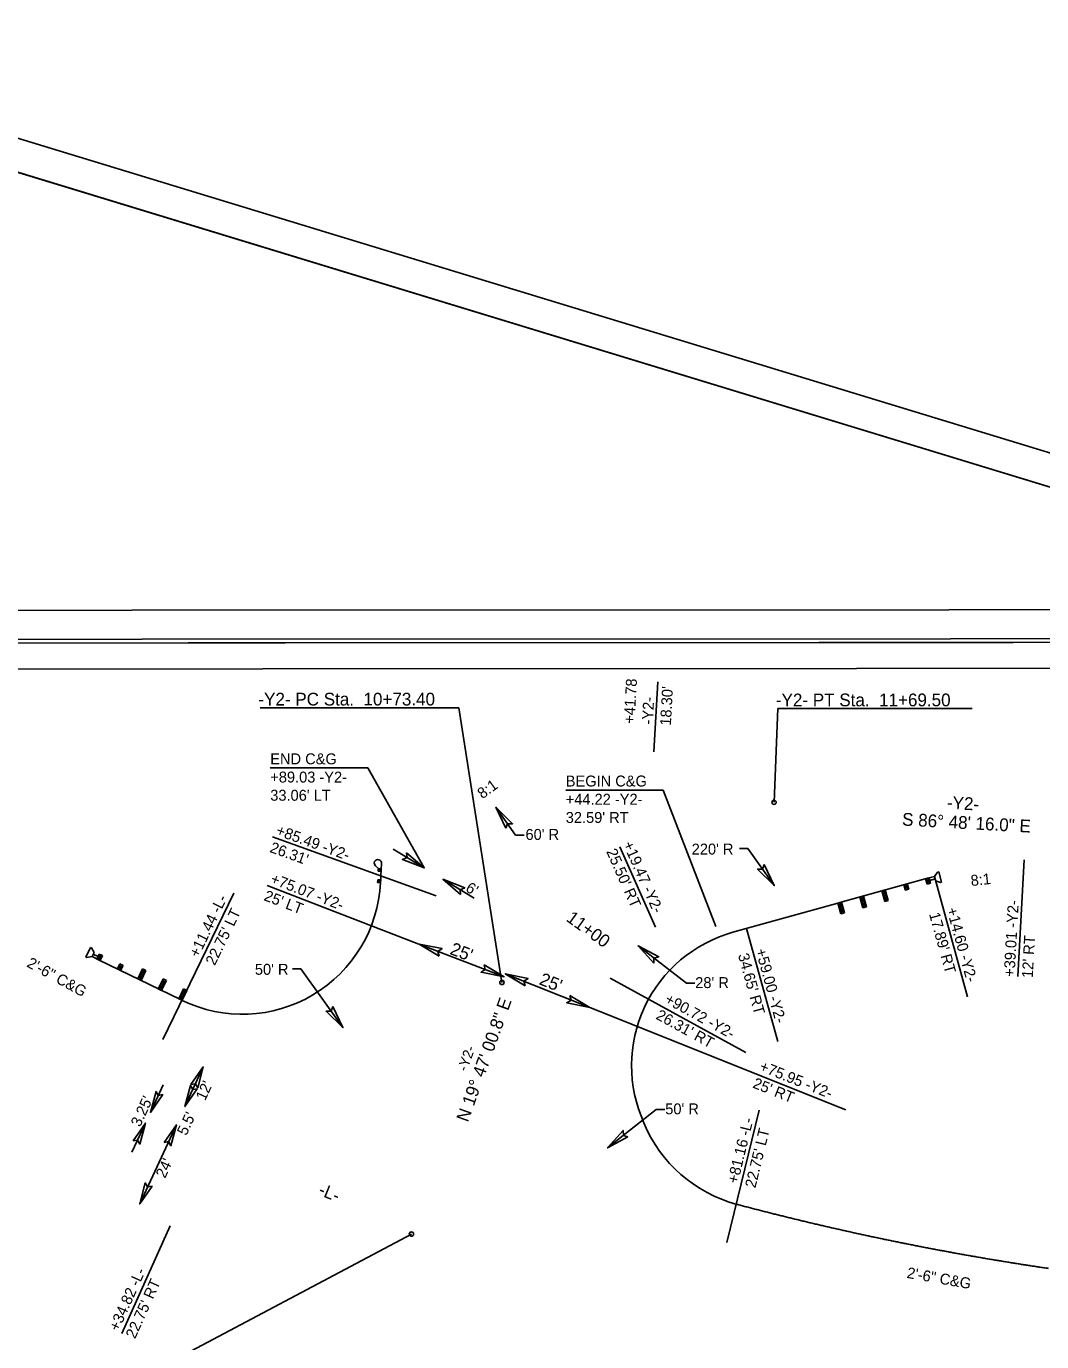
# Model space of a CAD drawing. Extents: x 1443477 to 1619989, y 756574 to 899826.
# Drawn here: x 1619422.9 to 1619701.9, y 898058.9 to 898420 of the extents above; entities that cross this region are included whole.
import ezdxf

# ---------------------------------------------------------------- set-up
doc = ezdxf.new("R2010")
doc.units = 0
for name, color, linetype in [('Default', 7, 'Continuous'), ('Prop Conc 2ft 6in Curb and Gutter', 7, 'Continuous'), ('Prop Dimension', 7, 'Continuous'), ('Prop Guardrail', 7, 'Continuous'), ('Prop Guardrail Anchor Unit CELL', 7, 'Continuous'), ('Prop Horizontal Alignment Direction Label', 7, 'Continuous'), ('Prop Horizontal Alignment Station Label', 7, 'Continuous'), ('Prop Shade Light', 7, 'Continuous'), ('Prop Terminator CELL', 7, 'Continuous'), ('Sheet Clip Boundary CELL', 7, 'Continuous'), ('Sheet Cutting Line CELL', 7, 'Continuous'), ('Sheet Layout Plan Border', 7, 'Continuous'), ('Sheet Plan CELL', 7, 'Continuous'), ('Sheet Plan Layout CELL', 7, 'Continuous'), ('Sheet Plot Border Inside CELL', 7, 'Continuous'), ('Sheet Plot Border Outside CELL', 7, 'Continuous')]:
    doc.layers.add(name, color=color, linetype=linetype)

msp = doc.modelspace()

# ---------------------------------------------------------------- linework, layer by layer
at = {"layer": 'Default'}
msp.add_lwpolyline([(1619324.8, 898243.59), (1619813.94, 898243.79), (1619813.98, 898167.39), (1619859.81, 898167.41), (1619859.94, 897863.4), (1619324.96, 897863.18)], close=True, dxfattribs=at)
at = {"layer": 'Prop Conc 2ft 6in Curb and Gutter'}
for p, q in [((1619516.75, 898216.42), (1619489.95, 898216.43)), ((1619532.25, 898188.96), (1619516.75, 898216.42)), ((1619597.92, 898210.34), (1619571.12, 898210.33)), ((1619597.92, 898210.34), (1619612.39, 898172.88)), ((1619479.98, 898182.06), (1619460.48, 898141.83)), ((1619620.58, 898138.32), (1619583.32, 898158.67)), ((1619624.22, 898122.48), (1619615.35, 898086.12)), ((1619462.43, 898090.71), (1619449.16, 898061.17))]:
    msp.add_line(p, q, dxfattribs=at)
at = {"layer": 'Prop Dimension'}
for p, q in [((1619596.44, 898240.1), (1619595.36, 898220.88)), ((1619551.94, 898205.63), (1619557.36, 898197.99)), ((1619490.53, 898197.48), (1619535.56, 898181.28)), ((1619559.68, 898197.99), (1619557.36, 898197.99)), ((1619532.25, 898188.96), (1619523.69, 898194.13)), ((1619585.96, 898194.78), (1619595.75, 898172.68)), ((1619621.18, 898194.28), (1619618.86, 898194.28)), ((1619628.39, 898184.15), (1619621.18, 898194.28)), ((1619695.29, 898159.19), (1619697.07, 898191.17)), ((1619537.38, 898185.85), (1619545.94, 898180.68)), ((1619681.52, 898153.63), (1619672.38, 898186.65)), ((1619530.8, 898168.08), (1619489.09, 898184.14)), ((1619629.35, 898141.35), (1619620.76, 898172.35)), ((1619554.16, 898159.09), (1619530.83, 898168.07)), ((1619590.98, 898167.56), (1619604.28, 898157.3)), ((1619498.39, 898161.27), (1619496.07, 898161.27)), ((1619509.89, 898145.13), (1619498.39, 898161.27)), ((1619554.49, 898159.91), (1619577.71, 898150.66)), ((1619606.6, 898157.31), (1619604.28, 898157.3)), ((1619577.71, 898150.66), (1619648.08, 898122.6)), ((1619466.5, 898123.48), (1619471.55, 898134.37)), ((1619457.02, 898121.86), (1619460.56, 898129.47)), ((1619582.59, 898112.12), (1619595.98, 898122.65)), ((1619598.3, 898122.65), (1619595.98, 898122.65)), ((1619451.96, 898110.94), (1619455.66, 898118.91)), ((1619454.08, 898096.72), (1619464.18, 898118.49))]:
    msp.add_line(p, q, dxfattribs=at)
at = {"layer": 'Prop Guardrail'}
msp.add_line((1619617.05, 898171.32), (1619645.9, 898179.32), dxfattribs=at)
for centre, radius, start, end in [((1619482.29, 898186.82), 38, 244.1387, 357.2224), ((1619627.2, 898134.7), 38, 105.4983, 204.4603), ((1619627.99, 898133.67), 38.34, 202.5753, 255.1149)]:
    msp.add_arc(centre, radius, start, end, dxfattribs=at)
for points in [[(1619656.5, 898087.47), (1619655.24, 898087.74), (1619654.6, 898087.88), (1619653.97, 898088.01), (1619653.34, 898088.15), (1619652.7, 898088.29), (1619652.07, 898088.42), (1619651.44, 898088.56), (1619650.8, 898088.7), (1619650.17, 898088.84), (1619649.54, 898088.98), (1619648.9, 898089.12), (1619648.27, 898089.26), (1619647.64, 898089.4), (1619647.01, 898089.54), (1619646.37, 898089.69), (1619645.74, 898089.83), (1619645.11, 898089.97), (1619644.48, 898090.12), (1619643.85, 898090.26), (1619643.22, 898090.41), (1619642.58, 898090.55), (1619641.95, 898090.7), (1619641.32, 898090.84), (1619640.69, 898090.99), (1619640.06, 898091.14), (1619639.43, 898091.29), (1619638.8, 898091.44), (1619638.17, 898091.58), (1619637.54, 898091.73), (1619636.91, 898091.88), (1619636.28, 898092.04), (1619635.65, 898092.19), (1619635.02, 898092.34), (1619634.39, 898092.49), (1619633.76, 898092.64), (1619633.13, 898092.8), (1619632.5, 898092.95), (1619631.87, 898093.11), (1619631.24, 898093.26), (1619630.62, 898093.42), (1619629.99, 898093.57), (1619629.36, 898093.73), (1619628.73, 898093.89), (1619628.1, 898094.04), (1619627.47, 898094.2), (1619626.85, 898094.36), (1619626.22, 898094.52), (1619625.59, 898094.68), (1619624.96, 898094.84), (1619624.34, 898095), (1619623.71, 898095.16), (1619623.08, 898095.32), (1619622.46, 898095.49), (1619621.83, 898095.65), (1619621.2, 898095.81), (1619620.58, 898095.98), (1619619.95, 898096.14), (1619619.32, 898096.31), (1619618.7, 898096.47), (1619618.14, 898096.62)], [(1619703.74, 898079.02), (1619702.45, 898079.21), (1619701.81, 898079.31), (1619701.17, 898079.4), (1619700.53, 898079.5), (1619699.89, 898079.6), (1619699.25, 898079.69), (1619698.6, 898079.79), (1619697.96, 898079.89), (1619697.32, 898079.99), (1619696.68, 898080.09), (1619696.04, 898080.19), (1619695.4, 898080.29), (1619694.76, 898080.39), (1619694.12, 898080.5), (1619693.48, 898080.6), (1619692.84, 898080.7), (1619692.2, 898080.81), (1619691.56, 898080.91), (1619690.92, 898081.01), (1619690.28, 898081.12), (1619689.64, 898081.23), (1619689, 898081.33), (1619688.36, 898081.44), (1619687.72, 898081.55), (1619687.08, 898081.65), (1619686.44, 898081.76), (1619685.8, 898081.87), (1619685.16, 898081.98), (1619684.52, 898082.09), (1619683.88, 898082.2), (1619683.24, 898082.31), (1619682.6, 898082.43), (1619681.96, 898082.54), (1619681.32, 898082.65), (1619680.69, 898082.76), (1619680.05, 898082.88), (1619679.41, 898082.99), (1619678.77, 898083.11), (1619678.13, 898083.22), (1619677.49, 898083.34), (1619676.86, 898083.46), (1619676.22, 898083.57), (1619675.58, 898083.69), (1619674.94, 898083.81), (1619674.31, 898083.93), (1619673.67, 898084.05), (1619673.03, 898084.17), (1619672.39, 898084.29), (1619671.76, 898084.41), (1619671.12, 898084.53), (1619670.48, 898084.65), (1619669.85, 898084.78), (1619669.21, 898084.9), (1619668.57, 898085.02), (1619667.94, 898085.15), (1619667.3, 898085.27), (1619666.67, 898085.4), (1619666.03, 898085.52), (1619665.39, 898085.65), (1619664.76, 898085.78), (1619664.12, 898085.9), (1619663.49, 898086.03), (1619662.85, 898086.16), (1619662.22, 898086.29), (1619661.58, 898086.42), (1619660.95, 898086.55), (1619660.31, 898086.68), (1619659.68, 898086.81), (1619659.04, 898086.94), (1619658.41, 898087.07), (1619657.77, 898087.21), (1619657.14, 898087.34), (1619656.5, 898087.47)]]:
    msp.add_spline(points, degree=3, dxfattribs=at)
at = {"layer": 'Prop Guardrail Anchor Unit CELL'}
for p, q in [((1619518.88, 898189.52), (1619519.81, 898188.75)), ((1619520.42, 898188.52), (1619520.5, 898190.24)), ((1619519.47, 898185.72), (1619519.44, 898185.02)), ((1619520.28, 898185.68), (1619519.44, 898185.02)), ((1619520.28, 898185.68), (1619519.47, 898185.72)), ((1619520.25, 898184.98), (1619519.47, 898185.72)), ((1619519.62, 898188.76), (1619519.59, 898188.06)), ((1619520.43, 898188.72), (1619519.59, 898188.06)), ((1619519.59, 898188.06), (1619520.39, 898188.02)), ((1619520.43, 898188.72), (1619519.62, 898188.76)), ((1619520.39, 898188.02), (1619519.62, 898188.76)), ((1619520.43, 898188.72), (1619520.08, 898188.74)), ((1619520.43, 898188.72), (1619520.08, 898188.74)), ((1619520.25, 898184.98), (1619520.42, 898188.52)), ((1619520.25, 898184.98), (1619520.28, 898185.68)), ((1619520.39, 898188.02), (1619520.43, 898188.72)), ((1619520.42, 898188.59), (1619520.41, 898188.46)), ((1619520.42, 898188.59), (1619520.41, 898188.46)), ((1619670.48, 898186.13), (1619646.38, 898179.45)), ((1619669.99, 898186), (1619670.96, 898186.27)), ((1619669.99, 898186), (1619670.4, 898184.54)), ((1619669.99, 898186), (1619671.36, 898184.8)), ((1619670.4, 898184.54), (1619670.96, 898186.27)), ((1619670.96, 898186.26), (1619672.38, 898186.65)), ((1619670.96, 898186.27), (1619671.36, 898184.8)), ((1619672.57, 898185.95), (1619671.15, 898185.56)), ((1619672.38, 898186.65), (1619673.28, 898187.79)), ((1619672.7, 898185.47), (1619672.38, 898186.65)), ((1619673.28, 898187.79), (1619673.58, 898187.87)), ((1619673.58, 898187.87), (1619674.36, 898185.04)), ((1619519.44, 898185.02), (1619520.25, 898184.98)), ((1619657.95, 898182.66), (1619658.91, 898182.93)), ((1619657.95, 898182.66), (1619658.76, 898179.73)), ((1619657.95, 898182.66), (1619659.32, 898181.46)), ((1619658.35, 898181.2), (1619658.91, 898182.93)), ((1619658.91, 898182.93), (1619659.72, 898180)), ((1619663.97, 898184.33), (1619664.93, 898184.6)), ((1619663.97, 898184.33), (1619664.38, 898182.87)), ((1619663.97, 898184.33), (1619665.34, 898183.13)), ((1619664.38, 898182.87), (1619664.93, 898184.6)), ((1619664.38, 898182.87), (1619665.34, 898183.13)), ((1619664.93, 898184.6), (1619665.34, 898183.13)), ((1619670.4, 898184.54), (1619671.36, 898184.8)), ((1619674.06, 898184.95), (1619672.7, 898185.47)), ((1619674.06, 898184.95), (1619674.36, 898185.04)), ((1619645.9, 898179.32), (1619646.87, 898179.59)), ((1619645.9, 898179.32), (1619646.71, 898176.39)), ((1619645.9, 898179.32), (1619647.27, 898178.12)), ((1619646.31, 898177.86), (1619646.87, 898179.59)), ((1619646.87, 898179.59), (1619647.68, 898176.66)), ((1619651.93, 898180.99), (1619652.89, 898181.26)), ((1619651.93, 898180.99), (1619652.74, 898178.06)), ((1619651.93, 898180.99), (1619653.29, 898179.79)), ((1619652.33, 898179.53), (1619652.89, 898181.26)), ((1619652.33, 898179.53), (1619653.29, 898179.79)), ((1619653.7, 898178.33), (1619652.33, 898179.53)), ((1619653.29, 898179.79), (1619652.74, 898178.06)), ((1619652.74, 898178.06), (1619653.7, 898178.33)), ((1619652.89, 898181.26), (1619653.7, 898178.33)), ((1619658.35, 898181.2), (1619659.32, 898181.46)), ((1619659.72, 898180), (1619658.35, 898181.2)), ((1619659.32, 898181.46), (1619658.76, 898179.73)), ((1619658.76, 898179.73), (1619659.72, 898180)), ((1619646.31, 898177.86), (1619647.27, 898178.12)), ((1619647.68, 898176.66), (1619646.31, 898177.86)), ((1619647.27, 898178.12), (1619646.71, 898176.39)), ((1619646.71, 898176.39), (1619647.68, 898176.66)), ((1619439.29, 898164.5), (1619440.58, 898167.14)), ((1619439.57, 898164.36), (1619439.29, 898164.5)), ((1619441, 898164.62), (1619439.57, 898164.36)), ((1619440.85, 898167.01), (1619440.58, 898167.14)), ((1619440.85, 898167.01), (1619441.54, 898165.72)), ((1619441.54, 898165.72), (1619441, 898164.62)), ((1619442.32, 898163.98), (1619441, 898164.62)), ((1619441.32, 898165.27), (1619442.64, 898164.63)), ((1619442.32, 898163.97), (1619442.98, 898165.34)), ((1619443.88, 898164.9), (1619442.32, 898163.97)), ((1619443.22, 898163.53), (1619442.32, 898163.97)), ((1619443.88, 898164.9), (1619442.98, 898165.34)), ((1619443.22, 898163.53), (1619442.98, 898165.34)), ((1619443.22, 898163.53), (1619443.88, 898164.9)), ((1619442.77, 898163.75), (1619465.27, 898152.85)), ((1619447.94, 898161.24), (1619448.61, 898162.61)), ((1619449.51, 898162.17), (1619447.94, 898161.24)), ((1619448.84, 898160.81), (1619447.94, 898161.24)), ((1619449.51, 898162.17), (1619448.61, 898162.61)), ((1619448.84, 898160.81), (1619448.61, 898162.61)), ((1619448.84, 898160.81), (1619449.51, 898162.17)), ((1619453.57, 898158.52), (1619454.89, 898161.25)), ((1619454.23, 898159.88), (1619455.79, 898160.81)), ((1619454.47, 898158.08), (1619455.79, 898160.81)), ((1619455.79, 898160.81), (1619454.89, 898161.25)), ((1619454.89, 898161.25), (1619455.13, 898159.45)), ((1619455.13, 898159.45), (1619453.57, 898158.52)), ((1619454.47, 898158.08), (1619453.57, 898158.52)), ((1619455.13, 898159.45), (1619454.23, 898159.88)), ((1619454.47, 898158.08), (1619454.23, 898159.88)), ((1619459.19, 898155.79), (1619460.52, 898158.52)), ((1619460.75, 898156.72), (1619459.19, 898155.79)), ((1619459.85, 898157.16), (1619461.42, 898158.09)), ((1619460.75, 898156.72), (1619459.85, 898157.16)), ((1619460.09, 898155.35), (1619459.85, 898157.16)), ((1619460.09, 898155.35), (1619461.42, 898158.09)), ((1619461.42, 898158.09), (1619460.52, 898158.52)), ((1619460.52, 898158.52), (1619460.75, 898156.72)), ((1619460.09, 898155.35), (1619459.19, 898155.79)), ((1619464.82, 898153.06), (1619466.14, 898155.8)), ((1619466.38, 898153.99), (1619464.82, 898153.06)), ((1619465.72, 898152.63), (1619464.82, 898153.06)), ((1619465.48, 898154.43), (1619467.04, 898155.36)), ((1619466.38, 898153.99), (1619465.48, 898154.43)), ((1619465.72, 898152.63), (1619465.48, 898154.43)), ((1619465.72, 898152.63), (1619467.04, 898155.36)), ((1619467.04, 898155.36), (1619466.14, 898155.8)), ((1619466.14, 898155.8), (1619466.38, 898153.99))]:
    msp.add_line(p, q, dxfattribs=at)
msp.add_ellipse((1619519.51, 898190.29), major_axis=(-0.992, 0.048), ratio=0.995379, start_param=3.141593, end_param=7.214552, dxfattribs=at)
at = {"layer": 'Prop Horizontal Alignment Station Label'}
for p, q in [((1619487.19, 898232.93), (1619541.75, 898232.95)), ((1619553.58, 898157.53), (1619541.75, 898232.95)), ((1619629.37, 898232.71), (1619628.34, 898207.02)), ((1619682.73, 898232.73), (1619629.37, 898232.71)), ((1619451.2, 898047.41), (1619528.74, 898088.46))]:
    msp.add_line(p, q, dxfattribs=at)
for centre in [(1619628.34, 898207.02), (1619553.58, 898157.53), (1619528.74, 898088.46)]:
    msp.add_circle(centre, 0.6, dxfattribs=at)
at = {"layer": 'Prop Shade Light'}
for p, q in [((1619670.09, 898185.91), (1619669.99, 898186)), ((1619669.99, 898186), (1619670.02, 898185.9)), ((1619670.02, 898185.9), (1619670.03, 898185.9))]:
    msp.add_line(p, q, dxfattribs=at)
msp.add_open_spline([(1619670.03, 898185.9), (1619670.05, 898185.91), (1619670.07, 898185.91), (1619670.09, 898185.91)], degree=2, dxfattribs=at)
at = {"layer": 'Prop Terminator CELL'}
for points in [[(1619554.7, 898199.86), (1619551.94, 898205.63), (1619556.52, 898201.11), (1619555.14, 898201.12)], [(1619527.41, 898193.15), (1619532.25, 898188.96), (1619526.24, 898191.28), (1619527.51, 898191.82)], [(1619625.62, 898189.91), (1619628.39, 898184.15), (1619623.81, 898188.66), (1619625.18, 898188.66)], [(1619542.21, 898181.67), (1619537.38, 898185.85), (1619543.39, 898183.54), (1619542.12, 898182.99)], [(1619536.32, 898164.79), (1619530.83, 898168.07), (1619537.15, 898166.84), (1619535.99, 898166.08)], [(1619595.31, 898162.85), (1619590.98, 898167.56), (1619596.68, 898164.58), (1619595.36, 898164.18)], [(1619548.67, 898162.36), (1619554.16, 898159.09), (1619547.85, 898160.32), (1619549, 898161.07)], [(1619559.94, 898156.57), (1619554.49, 898159.91), (1619560.79, 898158.61), (1619559.62, 898157.87)], [(1619572.26, 898154), (1619577.71, 898150.66), (1619571.41, 898151.96), (1619572.57, 898152.7)], [(1619507.12, 898150.89), (1619509.89, 898145.13), (1619505.3, 898149.64), (1619506.68, 898149.63)], [(1619468.17, 898129.49), (1619471.55, 898134.37), (1619470.01, 898128.59), (1619469.39, 898129.71)], [(1619469.87, 898128.37), (1619466.5, 898123.48), (1619468.03, 898129.26), (1619468.66, 898128.14)], [(1619460.4, 898126.74), (1619457.02, 898121.86), (1619458.56, 898127.63), (1619459.19, 898126.52)], [(1619452.28, 898114.03), (1619455.66, 898118.91), (1619454.12, 898113.14), (1619453.5, 898114.25)], [(1619460.8, 898113.61), (1619464.18, 898118.49), (1619462.65, 898112.72), (1619462.02, 898113.84)], [(1619588.21, 898115.16), (1619582.59, 898112.12), (1619586.88, 898116.91), (1619586.94, 898115.54)], [(1619457.46, 898101.61), (1619454.08, 898096.72), (1619455.61, 898102.5), (1619456.24, 898101.38)]]:
    msp.add_lwpolyline(points, close=True, dxfattribs=at)
at = {"layer": 'Sheet Clip Boundary CELL'}
msp.add_lwpolyline([(1619277.64, 897984.43), (1619813.32, 897821.17), (1619911.11, 898142), (1619838.69, 898164.07), (1619863.35, 898244.99), (1619400.09, 898386.19)], close=True, dxfattribs=at)
at = {"layer": 'Sheet Cutting Line CELL'}
msp.add_line((1619964.03, 898223.71), (1619319.88, 898420.04), dxfattribs=at)
at = {"layer": 'Sheet Layout Plan Border'}
msp.add_lwpolyline([(1619277.64, 897984.43), (1619813.32, 897821.17), (1619911.11, 898142), (1619838.69, 898164.07), (1619863.35, 898244.99), (1619400.09, 898386.19)], close=True, dxfattribs=at)
at = {"layer": 'Sheet Plan CELL'}
for points in [[(1619294.13, 897830.71), (1619293.94, 898250.7), (1619813.94, 898250.93), (1619813.97, 898190.91), (1619893.98, 898190.94), (1619894.13, 897830.96)], [(1619893.97, 898250.96), (1619293.95, 898250.71), (1619294.13, 897830.71), (1619894.13, 897830.96)]]:
    msp.add_lwpolyline(points, close=True, dxfattribs=at)
at = {"layer": 'Sheet Plan Layout CELL'}
msp.add_lwpolyline([(1619380.95, 898392.01), (1619258.51, 897990.27), (1619832.45, 897815.34), (1619930.23, 898136.17), (1619838.69, 898164.07), (1619863.35, 898244.99)], close=True, dxfattribs=at)
at = {"layer": 'Sheet Plot Border Inside CELL'}
msp.add_lwpolyline([(1619232.74, 897829.68), (1619899.13, 897829.97), (1619898.96, 898251.96), (1619232.56, 898251.68)], close=True, dxfattribs=at)
at = {"layer": 'Sheet Plot Border Outside CELL'}
msp.add_lwpolyline([(1619227.54, 897821.68), (1619900.94, 897821.96), (1619900.76, 898259.96), (1619227.36, 898259.68)], close=True, dxfattribs=at)

# ---------------------------------------------------------------- texts
at = {"layer": 'Prop Conc 2ft 6in Curb and Gutter'}
for s, rotation, p in [('END C&G', 359.9685, (1619489.95, 898217.43)), ('+89.03 -Y2-', 359.9685, (1619489.95, 898212.43)), ('BEGIN C&G', 0.0239, (1619571.12, 898211.33)), ("33.06' LT", 359.9685, (1619489.95, 898207.43)), ('+44.22 -Y2-', 0.0239, (1619571.12, 898206.33)), ("32.59' RT", 0.0239, (1619571.12, 898201.33)), ('+11.44 -L-', 64.1387, (1619470.2, 898164.16)), ("22.75' LT", 64.1387, (1619474.7, 898161.98)), ('+90.72 -Y2-', 331.351, (1619598.05, 898152.06)), ("26.31' RT", 331.351, (1619595.65, 898147.67)), ('+81.16 -L-', 76.2942, (1619618.35, 898102.12)), ("22.75' LT", 76.2942, (1619623.21, 898100.94)), ('+34.82 -L-', 65.8136, (1619448.25, 898061.58)), ("22.75' RT", 65.8136, (1619452.81, 898059.53))]:
    msp.add_text(s, height=3, rotation=rotation, dxfattribs=at).set_placement(p)
at = {"layer": 'Prop Dimension'}
for s, height, rotation, p in [('+41.78', 3, 86.8045, (1619590.01, 898228.52)), ("18.30'", 3, 86.8045, (1619599.99, 898227.97)), ('-Y2-', 3, 86.8045, (1619595, 898228.25)), ('8:1', 3, 35.7834, (1619548.21, 898207.81)), ('+85.49 -Y2-', 3, 340.2164, (1619491.3, 898198.1)), ("60' R", 3, 0.0239, (1619560.06, 898196.67)), ("26.31'", 3, 340.2164, (1619489.61, 898193.39)), ("25.50' RT", 3, 293.8787, (1619582.19, 898193.5)), ('+19.47 -Y2-', 3, 293.8787, (1619586.77, 898195.52)), ("220' R", 3, 0.0239, (1619605.72, 898192.65)), ('+75.07 -Y2-', 3, 338.9436, (1619489.76, 898184.84)), ('8:1', 3, 6.267, (1619682.51, 898183.98)), ("25' LT", 3, 338.9436, (1619487.97, 898180.18)), ("6'", 3, 328.8526, (1619543.36, 898182.73)), ('+39.01 -Y2-', 3, 86.8045, (1619694.41, 898158.99)), ("17.89' RT", 3, 285.4846, (1619670.88, 898176.36)), ('+14.60 -Y2-', 3, 285.4846, (1619675.7, 898177.69)), ("25'", 3.5, 338.9436, (1619539.06, 898165.4)), ("12' RT", 3, 86.8045, (1619699.4, 898158.71)), ('2\'-6" C&G', 3, 331.3218, (1619422.83, 898161.99)), ("34.65' RT", 3, 285.4846, (1619618.4, 898165.09)), ('+59.00 -Y2-', 3, 285.4846, (1619623.22, 898166.42)), ("50' R", 3, 0.0239, (1619485.72, 898159.64)), ("25'", 3.5, 338.2654, (1619563.59, 898157.09)), ("28' R", 3, 0.0239, (1619606.69, 898155.99)), ('+75.95 -Y2-', 3, 338.2654, (1619624.1, 898133.37)), ("12'", 3, 65.1101, (1619472.04, 898124.87)), ("25' RT", 3, 338.2654, (1619622.25, 898128.73)), ("3.25'", 3, 65.1101, (1619454.19, 898117.67)), ("50' R", 3, 0.0239, (1619598.45, 898121.33)), ("5.5'", 3, 65.1101, (1619466.9, 898115.3)), ("24'", 3, 65.1101, (1619461.05, 898103.59)), ('2\'-6" C&G', 3, 349.9517, (1619664.67, 898076.45))]:
    msp.add_text(s, height=height, rotation=rotation, dxfattribs=at).set_placement(p)
at = {"layer": 'Prop Horizontal Alignment Direction Label'}
for s, height, rotation, p in [('-Y2-', 3.5, 356.8045, (1619675.75, 898205.21)), ('S 86%%d 48\' 16.0" E', 3.5, 356.8045, (1619663.44, 898200.64)), ('N 19%%d 47\' 00.8" E', 3.5, 70.2164, (1619544.25, 898118.99)), ('-Y2-', 2.8, 70.2164, (1619543.92, 898132.9)), ('-L-', 3.5, 338.0474, (1619502.92, 898099.34))]:
    msp.add_text(s, height=height, rotation=rotation, dxfattribs=at).set_placement(p)
at = {"layer": 'Prop Horizontal Alignment Station Label'}
for s, rotation, p in [('-Y2- PC Sta.  10+73.40', 0.0239, (1619486.69, 898233.56)), ('-Y2- PT Sta.  11+69.50', 0.0239, (1619628.84, 898233.34)), ('11+00', 324.0397, (1619571.01, 898174.6))]:
    msp.add_text(s, height=3.5, rotation=rotation, dxfattribs=at).set_placement(p)

doc.saveas('drawing.dxf')
